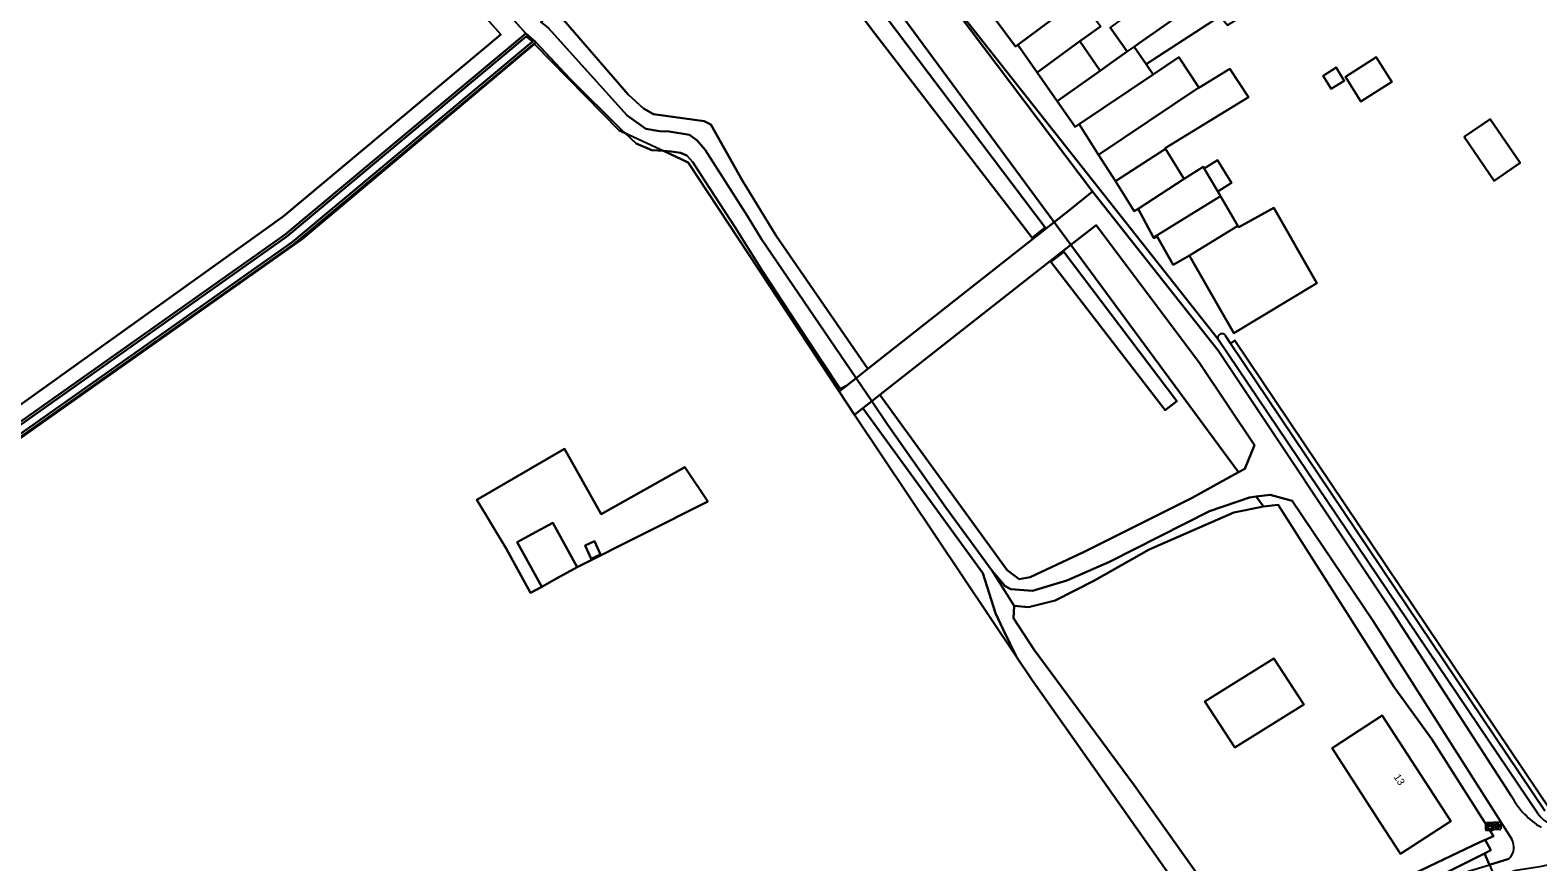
# Model space of a CAD drawing. Extents: x 163859 to 164644, y 379566 to 382155.
# Drawn here: x 164174.8 to 164380.2, y 381594.2 to 381707.4 of the extents above; entities that cross this region are included whole.
import ezdxf

# ---------------------------------------------------------------- set-up
doc = ezdxf.new("R2010")
doc.units = 0
for name, color, linetype in [('IMGEO_Bouwland', 7, 'Continuous'), ('IMGEO_Erf', 7, 'Continuous'), ('IMGEO_Grasland_overig', 7, 'Continuous'), ('IMGEO_Greppel_droge_sloot', 7, 'Continuous'), ('IMGEO_Groenvoorziening', 7, 'Continuous'), ('IMGEO_Haag', 7, 'Continuous'), ('IMGEO_Hek', 7, 'Continuous'), ('IMGEO_Kast', 7, 'Continuous'), ('IMGEO_Loofbos', 7, 'Continuous'), ('IMGEO_Oever', 7, 'Continuous'), ('IMGEO_Pand', 7, 'Continuous'), ('IMGEO_Pand_nummerreeks', 7, 'Continuous'), ('IMGEO_Rijbaan_lokaal_onverhard', 7, 'Continuous'), ('IMGEO_Rioolput', 7, 'Continuous'), ('IMGEO_Terreindeel_onvherhard', 7, 'Continuous'), ('IMGEO_Voetpad_onverhard', 7, 'Continuous'), ('IMGEO_Waterloop', 7, 'Continuous')]:
    doc.layers.add(name, color=color, linetype=linetype)

msp = doc.modelspace()

# ---------------------------------------------------------------- linework, layer by layer
at = {"layer": 'IMGEO_Bouwland'}
msp.add_lwpolyline([(164337.15, 381582.3), (164311.21, 381619.04), (164309.17, 381622.09), (164287.09, 381655.07), (164285.01, 381658.22), (164264.42, 381689.42), (164261.07, 381690.98), (164259.49, 381691.08), (164257.35, 381692.01), (164255.85, 381693.41), (164255.02, 381693.79), (164243.51, 381705.53), (164243.4, 381705.47), (164211.9, 381679.04), (164123.79, 381616.85)], dxfattribs=at)
msp.add_lwpolyline([(164239.63, 381636.86), (164235.65, 381643.49), (164247.59, 381650.43), (164252.57, 381641.51), (164264, 381647.94), (164267.11, 381643.27), (164249.31, 381634.3), (164246.48, 381632.75), (164244.48, 381631.65), (164242.95, 381630.81)], close=True, dxfattribs=at)
at = {"layer": 'IMGEO_Erf'}
for points in [[(164381.89, 381725.72), (164366.58, 381736.25), (164365.24, 381734.41), (164343.09, 381750), (164341.65, 381751.02), (164341.73, 381751.2), (164335.58, 381755.47), (164335.67, 381755.63), (164322.06, 381765.02), (164322.9, 381766.25), (164322.17, 381766.72), (164321.2, 381765.27), (164309.22, 381773.47), (164309.77, 381774.13), (164309.53, 381774.29), (164308.75, 381773.28), (164308.4, 381772.83), (164307.02, 381771.02), (164290.86, 381750), (164280.77, 381736.89), (164280.48, 381736.47), (164297.43, 381715.02), (164336.62, 381665.42)], [(164336.94, 381709.34), (164326.85, 381702.82), (164327.82, 381701.41), (164331.32, 381703.75), (164334.02, 381699.61), (164334.03, 381699.59), (164338.24, 381702.16), (164340.77, 381698.29), (164329.42, 381691.37), (164329.49, 381691.26), (164331.91, 381687.38), (164332.04, 381687.18), (164334.62, 381688.84), (164334.75, 381688.61), (164336.58, 381689.74), (164338.49, 381686.65), (164336.59, 381685.48), (164336.97, 381684.84), (164339.35, 381680.78), (164339.47, 381680.59), (164344.25, 381683.23), (164350.11, 381673), (164338.78, 381666.16), (164332.93, 381676.4), (164332.74, 381676.73), (164330.52, 381675.46), (164328.33, 381679.34), (164327.91, 381679.13), (164327.86, 381679.22), (164325.75, 381683.12), (164325.23, 381682.79), (164322.65, 381686.86), (164320.35, 381690.47), (164317.7, 381694.63), (164317.19, 381694.29), (164314.73, 381697.78), (164312.01, 381701.68), (164309.36, 381705.43), (164309.06, 381705.2), (164306.26, 381708.94)], [(164320.61, 381707.93), (164318.4, 381706.36), (164317.82, 381705.94), (164320.58, 381701.9), (164322.4, 381703.19), (164324.28, 381704.52), (164321.94, 381707.78)], [(164337.65, 381665.82), (164338.35, 381664.78), (164338.92, 381665.18), (164382.05, 381601.1), (164407.63, 381605.35), (164407.8, 381604.43), (164409.37, 381604.7), (164409.29, 381605.07), (164413.47, 381605.82), (164413.71, 381604.01), (164429.61, 381607.59), (164435.64, 381608.59)]]:
    msp.add_lwpolyline(points, dxfattribs=at)
for points in [[(164353.83, 381700.54), (164352.04, 381699.45), (164350.95, 381701.23), (164352.74, 381702.33)], [(164356.12, 381697.73), (164353.99, 381701.1), (164358.18, 381703.74), (164360.31, 381700.38)], [(164370.16, 381692.91), (164373.7, 381695.33), (164377.8, 381689.35), (164374.26, 381686.92)], [(164360.65, 381617.95), (164344.82, 381642.8), (164342.85, 381642.58), (164338.8, 381641.77), (164327.26, 381636.72), (164319.71, 381632.45), (164314.46, 381629.79), (164310.8, 381628.87), (164308.85, 381629.06), (164308.78, 381627.38), (164311.6, 381623.07), (164325.22, 381604.63), (164340.03, 381583.8), (164340.63, 381582.95), (164341.72, 381582.81), (164360.39, 381591.19), (164372.33, 381596.86), (164373.03, 381597.19), (164374.16, 381597.69), (164365.76, 381610.9)], [(164338.91, 381609.75), (164334.83, 381616.04), (164344.23, 381621.88), (164348.31, 381615.59)], [(164358.78, 381599.46), (164352.17, 381609.65), (164354.82, 381611.38), (164359.01, 381614.1), (164368.35, 381599.71), (164361.5, 381595.27)]]:
    msp.add_lwpolyline(points, close=True, dxfattribs=at)
msp.add_arc((164337.17, 381665.55), 0.556, 29.6547, 192.9812, dxfattribs=at)
at = {"layer": 'IMGEO_Grasland_overig'}
for points in [[(164246.32, 381710.17), (164244.37, 381708.52), (164244.89, 381708.11), (164245.41, 381707.7), (164256.11, 381695.82), (164258.69, 381693.98), (164260.55, 381693.7), (164261.84, 381693.63), (164264.63, 381693.16), (164265.68, 381692.42), (164266.74, 381691.13), (164272.54, 381682.12), (164274.44, 381678.97), (164287.33, 381660.05), (164288.9, 381661.31), (164276.44, 381679.42), (164271.82, 381687), (164267.52, 381694.58), (164266.6, 381695.05), (164259.73, 381695.98), (164258.36, 381696.75), (164256.26, 381698.68)], [(164286.07, 381659.06), (164285.16, 381658.59), (164280.25, 381666), (164274.54, 381674.72), (164270.81, 381680.67), (164266.71, 381686.93), (164265.08, 381689.47), (164264.27, 381690.36), (164263.4, 381690.74), (164262.13, 381690.91), (164261.07, 381690.98), (164264.42, 381689.42), (164285.01, 381658.22)], [(164316.58, 381678.2), (164314.3, 381681.31), (164288.9, 381661.31), (164287.33, 381660.05), (164289.46, 381656.93), (164290.56, 381657.79)], [(164287.33, 381660.05), (164286.07, 381659.06), (164285.01, 381658.22), (164287.09, 381655.07), (164288.22, 381655.95), (164289.46, 381656.93)], [(164288.22, 381655.95), (164287.09, 381655.07), (164309.17, 381622.09), (164307.37, 381625.84), (164306.3, 381628.05), (164304.6, 381633.51)]]:
    msp.add_lwpolyline(points, close=True, dxfattribs=at)
msp.add_lwpolyline([(164321.9, 381568.69), (164330.62, 381575.1), (164340.85, 381580.53), (164344.81, 381582.22), (164350.33, 381584.74), (164362.79, 381589.53), (164367.77, 381592.02), (164373.62, 381593.79), (164372.93, 381595.33), (164360.91, 381589.33), (164342.17, 381581.51), (164338.17, 381581.17), (164320.74, 381570.88), (164310.1, 381564.69), (164300.85, 381559.61), (164287.59, 381552.54), (164276.47, 381546.15), (164268.74, 381541.65), (164255.73, 381530.58), (164258.3, 381529.24)], dxfattribs=at)
at = {"layer": 'IMGEO_Greppel_droge_sloot'}
msp.add_lwpolyline([(164291.43, 381709.22), (164290.57, 381710.43), (164290.47, 381710.57), (164288.39, 381708.97), (164289.4, 381707.55), (164311.33, 381679.17), (164313.1, 381680.56)], close=True, dxfattribs=at)
at = {"layer": 'IMGEO_Groenvoorziening'}
for points in [[(164297.43, 381715.02), (164297.33, 381714.93), (164319.55, 381685.45), (164336.67, 381663.83), (164360.3, 381628.34), (164376.68, 381603.04)], [(164380.22, 381600.77), (164336.62, 381665.42), (164297.43, 381715.02)], [(164383.73, 381600.26), (164407.8, 381604.43), (164407.63, 381605.35), (164382.05, 381601.1), (164338.92, 381665.18), (164338.35, 381664.78)], [(164338.35, 381664.78), (164381.18, 381601.12)], [(164357.73, 381627.06), (164346.74, 381643.35), (164343.74, 381644.16), (164341.85, 381643.92), (164342.85, 381642.58), (164344.82, 381642.8), (164360.65, 381617.95), (164365.76, 381610.9), (164374.16, 381597.69), (164373.03, 381597.19), (164373.82, 381595.78), (164372.93, 381595.33), (164373.62, 381593.79), (164376.28, 381594.59)], [(164376.65, 381597.28), (164357.73, 381627.06)]]:
    msp.add_lwpolyline(points, dxfattribs=at)
for points in [[(164334.05, 381662.17), (164320.02, 381680.9), (164316.58, 381678.2), (164339.41, 381647.23), (164340.27, 381647.7), (164341.63, 381650.93)], [(164327.26, 381636.72), (164338.8, 381641.77), (164342.85, 381642.58), (164341.85, 381643.92), (164340.91, 381643.8), (164335.47, 381641.94), (164321.84, 381635.05), (164316.04, 381632.51), (164311.35, 381631.09), (164308.41, 381631.32), (164307.64, 381631.71), (164305.88, 381633.83), (164308.85, 381629.06), (164310.8, 381628.87), (164314.46, 381629.79), (164319.71, 381632.45)]]:
    msp.add_lwpolyline(points, close=True, dxfattribs=at)
for centre, radius, start, end in [((164386.24, 381608.19), 10.85, 208.3188, 239.0619), ((164383.39, 381602.82), 3.78, 212.9561, 287.5967), ((164374.79, 381596.17), 2.17, 313.3238, 30.8642)]:
    msp.add_arc(centre, radius, start, end, dxfattribs=at)
at = {"layer": 'IMGEO_Haag'}
for points in [[(164383.73, 381600.26), (164407.8, 381604.43), (164407.63, 381605.35), (164382.05, 381601.1), (164338.92, 381665.18), (164338.35, 381664.78)], [(164338.35, 381664.78), (164381.18, 381601.12)]]:
    msp.add_lwpolyline(points, dxfattribs=at)
at = {"layer": 'IMGEO_Hek'}
for points in [[(164285.01, 381658.22), (164264.42, 381689.42), (164255.02, 381693.79), (164243.51, 381705.53), (164243.36, 381705.52)], [(164287.09, 381655.07), (164285.01, 381658.22)]]:
    msp.add_lwpolyline(points, dxfattribs=at)
at = {"layer": 'IMGEO_Kast'}
for p, q in [((164373.2, 381599.49), (164374.04, 381599.49)), ((164374.04, 381599.49), (164373.2, 381599.49)), ((164373.12, 381598.57), (164373.12, 381599.41)), ((164373.12, 381599.41), (164373.12, 381598.57)), ((164374.05, 381598.49), (164373.21, 381598.49)), ((164373.21, 381598.49), (164374.05, 381598.49)), ((164374.12, 381599.42), (164374.12, 381598.58)), ((164374.12, 381598.58), (164374.12, 381599.42))]:
    msp.add_line(p, q, dxfattribs=at)
for points in [[(164373.32, 381599.28), (164373.92, 381599.28), (164373.92, 381599.2), (164373.32, 381599.2), (164373.32, 381599.28)], [(164373.32, 381599.11), (164373.92, 381599.11), (164373.92, 381598.62), (164373.32, 381598.62), (164373.32, 381599.11)]]:
    msp.add_lwpolyline(points, dxfattribs=at)
msp.add_circle((164373.4, 381598.96), 0.0377, dxfattribs=at)
for centre, start, end in [((164373.2, 381599.41), 92.4484, 184.2845), ((164373.2, 381599.41), 92.4484, 184.2845), ((164374.04, 381599.41), 2.4484, 94.2845), ((164374.04, 381599.41), 2.4484, 94.2845), ((164373.2, 381598.57), 182.4484, 274.2845), ((164373.2, 381598.57), 182.4484, 274.2845), ((164374.04, 381598.57), 272.4484, 4.2845), ((164374.04, 381598.57), 272.4484, 4.2845)]:
    msp.add_arc(centre, 0.0779, start, end, dxfattribs=at)
at = {"layer": 'IMGEO_Loofbos'}
for points in [[(164292.53, 381710.83), (164296.62, 381714.32), (164283.66, 381730.8), (164279.12, 381735.74), (164248.87, 381710.58), (164248.44, 381711.09), (164248.01, 381711.61), (164246.32, 381710.17), (164256.26, 381698.68), (164258.36, 381696.75), (164259.73, 381695.98), (164266.6, 381695.05), (164267.52, 381694.58), (164271.82, 381687), (164276.44, 381679.42), (164288.9, 381661.31), (164314.3, 381681.31)], [(164289.4, 381707.55), (164288.39, 381708.97), (164290.47, 381710.57), (164290.57, 381710.43), (164291.43, 381709.22), (164313.1, 381680.56), (164311.33, 381679.17)], [(164339.41, 381647.23), (164316.58, 381678.2), (164290.56, 381657.79), (164307.9, 381633.89), (164309.52, 381632.67), (164311.06, 381632.96), (164318.32, 381636.36), (164333.13, 381643.77)], [(164315.64, 381677.27), (164331.04, 381656.92), (164329.45, 381655.7), (164313.88, 381675.88)]]:
    msp.add_lwpolyline(points, close=True, dxfattribs=at)
msp.add_lwpolyline([(164162.11, 381648.34), (164209.26, 381682.06), (164238.9, 381706.83), (164214.34, 381734.46), (164210.77, 381733.46), (164209.5, 381733.38), (164208.24, 381733.18), (164207.01, 381732.88), (164205.81, 381732.47), (164204.64, 381731.95), (164204.45, 381731.85), (164130.93, 381680.28)], dxfattribs=at)
at = {"layer": 'IMGEO_Oever'}
for points in [[(164210.69, 381678.29), (164243.36, 381705.52), (164243.68, 381705.78), (164242.3, 381706.96), (164209.54, 381679.61), (164044.56, 381563.04), (164045.08, 381561.59)], [(164243.14, 381705.78), (164210.48, 381678.57), (164045.25, 381562.13), (164044.98, 381562.91), (164209.75, 381679.34), (164242.36, 381706.56), (164243.26, 381705.89)]]:
    msp.add_lwpolyline(points, close=True, dxfattribs=at)
at = {"layer": 'IMGEO_Pand'}
for points in [[(164347.48, 381714.07), (164344.1, 381718.5), (164334.47, 381711.7), (164325.91, 381705.67), (164325.22, 381705.18), (164326.85, 381702.82), (164336.94, 381709.34), (164337.91, 381708.11)], [(164334.47, 381711.7), (164333.03, 381713.59), (164331.95, 381715), (164321.94, 381707.78), (164324.28, 381704.52), (164325.22, 381705.18), (164325.91, 381705.67)], [(164316.22, 381710.54), (164313.3, 381714.42), (164306.26, 381708.94), (164309.06, 381705.2), (164309.36, 381705.43)], [(164316.22, 381710.54), (164309.36, 381705.43), (164312.01, 381701.68), (164317.82, 381705.94), (164318.4, 381706.36), (164320.61, 381707.93), (164317.82, 381711.73)], [(164317.82, 381705.94), (164312.01, 381701.68), (164314.73, 381697.78), (164320.58, 381701.9)], [(164327.82, 381701.41), (164326.85, 381702.82), (164325.22, 381705.18), (164324.28, 381704.52), (164322.4, 381703.19), (164320.58, 381701.9), (164314.73, 381697.78), (164317.19, 381694.29), (164317.7, 381694.63)], [(164334.02, 381699.61), (164331.32, 381703.75), (164327.82, 381701.41), (164317.7, 381694.63), (164320.35, 381690.47)], [(164322.65, 381686.86), (164329.49, 381691.26), (164329.42, 381691.37), (164340.77, 381698.29), (164338.24, 381702.16), (164334.03, 381699.59), (164334.02, 381699.61), (164320.35, 381690.47)], [(164350.95, 381701.23), (164352.04, 381699.45), (164353.83, 381700.54), (164352.74, 381702.33)], [(164358.18, 381703.74), (164353.99, 381701.1), (164356.12, 381697.73), (164360.31, 381700.38)], [(164370.16, 381692.91), (164374.26, 381686.92), (164377.8, 381689.35), (164373.7, 381695.33)], [(164332.04, 381687.18), (164331.91, 381687.38), (164329.49, 381691.26), (164322.65, 381686.86), (164325.23, 381682.79), (164325.75, 381683.12)], [(164336.97, 381684.84), (164336.59, 381685.48), (164334.75, 381688.61), (164334.62, 381688.84), (164332.04, 381687.18), (164325.75, 381683.12), (164327.86, 381679.22)], [(164334.75, 381688.61), (164336.59, 381685.48), (164338.49, 381686.65), (164336.58, 381689.74)], [(164327.86, 381679.22), (164327.91, 381679.13), (164328.33, 381679.34), (164330.52, 381675.46), (164332.74, 381676.73), (164339.35, 381680.78), (164336.97, 381684.84)], [(164339.35, 381680.78), (164332.74, 381676.73), (164332.93, 381676.4), (164338.78, 381666.16), (164350.11, 381673), (164344.25, 381683.23), (164339.47, 381680.59)], [(164244.48, 381631.65), (164246.48, 381632.75), (164249.31, 381634.3), (164245.99, 381640.35), (164243.15, 381638.8), (164241.16, 381637.7)], [(164250.4, 381637.24), (164251.23, 381635.44), (164252.51, 381636.03), (164251.69, 381637.84)], [(164338.91, 381609.75), (164348.31, 381615.59), (164344.23, 381621.88), (164334.83, 381616.04)], [(164361.5, 381595.27), (164368.35, 381599.71), (164359.01, 381614.1), (164354.82, 381611.38), (164352.17, 381609.65), (164358.78, 381599.46)]]:
    msp.add_lwpolyline(points, close=True, dxfattribs=at)
at = {"layer": 'IMGEO_Rijbaan_lokaal_onverhard'}
msp.add_lwpolyline([(164297.33, 381714.93), (164296.62, 381714.32), (164292.53, 381710.83), (164314.3, 381681.31), (164316.43, 381682.99), (164319.55, 381685.45)], close=True, dxfattribs=at)
for points in [[(164376.68, 381603.04), (164360.3, 381628.34), (164336.67, 381663.83), (164319.55, 381685.45), (164316.43, 381682.99), (164314.3, 381681.31), (164316.58, 381678.2), (164320.02, 381680.9), (164334.05, 381662.17), (164341.63, 381650.93), (164340.27, 381647.7), (164339.41, 381647.23), (164333.13, 381643.77), (164318.32, 381636.36), (164311.06, 381632.96), (164309.52, 381632.67), (164307.9, 381633.89), (164290.56, 381657.79), (164289.46, 381656.93), (164291.61, 381653.76), (164299.54, 381642.42), (164305.88, 381633.83), (164307.64, 381631.71), (164308.41, 381631.32), (164311.35, 381631.09), (164316.04, 381632.51), (164321.84, 381635.05), (164335.47, 381641.94), (164340.91, 381643.8), (164341.85, 381643.92), (164343.74, 381644.16), (164346.74, 381643.35), (164357.73, 381627.06), (164376.65, 381597.28)], [(164376.28, 381594.59), (164373.62, 381593.79), (164374.37, 381592.06), (164377.23, 381593.05), (164380.51, 381593.56), (164384.86, 381594.48), (164414.14, 381600.68)]]:
    msp.add_lwpolyline(points, dxfattribs=at)
for centre, radius, start, end in [((164386.24, 381608.19), 10.85, 208.3188, 239.0619), ((164374.79, 381596.17), 2.17, 313.3238, 30.8642)]:
    msp.add_arc(centre, radius, start, end, dxfattribs=at)
at = {"layer": 'IMGEO_Rioolput'}
for p, q in [((164374.16, 381598.66), (164374.16, 381599.51)), ((164374.23, 381599.59), (164375.08, 381599.59)), ((164375.16, 381599.51), (164375.16, 381598.66)), ((164375.08, 381598.59), (164374.23, 381598.59)), ((164374.41, 381599.08), (164374.41, 381599.09)), ((164374.85, 381599.04), (164374.45, 381599.04)), ((164374.46, 381599.13), (164374.85, 381599.13)), ((164374.64, 381599.37), (164374.67, 381599.37)), ((164374.67, 381598.81), (164374.64, 381598.81)), ((164374.9, 381599.09), (164374.9, 381599.08))]:
    msp.add_line(p, q, dxfattribs=at)
for points in [[(164374.16, 381598.66), (164374.16, 381599.51)], [(164374.23, 381599.59), (164375.08, 381599.59)], [(164375.16, 381599.51), (164375.16, 381598.66)], [(164375.08, 381598.59), (164374.23, 381598.59)]]:
    msp.add_lwpolyline(points, dxfattribs=at)
for centre, radius, start, end in [((164374.23, 381599.51), 0.0765, 91.552, 178.448), ((164374.23, 381599.51), 0.0765, 91.552, 178.448), ((164375.08, 381599.51), 0.0765, 1.552, 88.448), ((164375.08, 381599.51), 0.0765, 1.552, 88.448), ((164374.23, 381598.66), 0.0765, 181.552, 268.448), ((164374.23, 381598.66), 0.0765, 181.552, 268.448), ((164374.45, 381599.09), 0.0403, 85.8775, 175.7526), ((164374.45, 381599.08), 0.0366, 178.938, 274.7102), ((164374.86, 381599.09), 0.0386, 1.7309, 96.639), ((164374.86, 381599.09), 0.043, 264.8664, 352.4533), ((164375.08, 381598.66), 0.0765, 271.552, 358.448), ((164375.08, 381598.66), 0.0765, 271.552, 358.448)]:
    msp.add_arc(centre, radius, start, end, dxfattribs=at)
for centre, major_axis, ratio, start_param, end_param in [((164374.64, 381599.09), (-0.387, 0.002), 0.722429, 4.712389, 7.853982), ((164374.67, 381599.09), (-0.39, 0.002), 0.717154, 1.570796, 4.712389)]:
    msp.add_ellipse(centre, major_axis=major_axis, ratio=ratio, start_param=start_param, end_param=end_param, dxfattribs=at)
at = {"layer": 'IMGEO_Terreindeel_onvherhard'}
for points in [[(164247.59, 381650.43), (164235.65, 381643.49), (164239.63, 381636.86), (164242.95, 381630.81), (164244.48, 381631.65), (164241.16, 381637.7), (164243.15, 381638.8), (164245.99, 381640.35), (164249.31, 381634.3), (164267.11, 381643.27), (164264, 381647.94), (164252.57, 381641.51)], [(164251.69, 381637.84), (164252.51, 381636.03), (164251.23, 381635.44), (164250.4, 381637.24)]]:
    msp.add_lwpolyline(points, close=True, dxfattribs=at)
at = {"layer": 'IMGEO_Voetpad_onverhard'}
for points in [[(164044.56, 381563.04), (164209.54, 381679.61), (164242.3, 381706.96), (164217.89, 381734.38)], [(164130.93, 381680.28), (164204.45, 381731.85), (164204.64, 381731.95), (164205.81, 381732.47), (164207.01, 381732.88), (164208.24, 381733.18), (164209.5, 381733.38), (164210.77, 381733.46), (164214.34, 381734.46), (164238.9, 381706.83), (164209.26, 381682.06), (164162.11, 381648.34)], [(164123.79, 381616.85), (164211.9, 381679.04), (164243.4, 381705.47), (164243.51, 381705.53), (164255.02, 381693.79), (164255.85, 381693.41), (164255.36, 381693.87), (164248.33, 381700.83), (164243.68, 381705.78), (164243.36, 381705.52), (164210.69, 381678.29), (164045.08, 381561.59)]]:
    msp.add_lwpolyline(points, dxfattribs=at)
at = {"layer": 'IMGEO_Waterloop'}
for points in [[(164217.89, 381734.38), (164242.3, 381706.96), (164243.68, 381705.78), (164248.33, 381700.83), (164255.36, 381693.87), (164255.85, 381693.41), (164257.35, 381692.01), (164259.49, 381691.08), (164261.07, 381690.98), (164262.13, 381690.91), (164263.4, 381690.74), (164264.27, 381690.36), (164265.08, 381689.47), (164266.71, 381686.93), (164270.81, 381680.67), (164274.54, 381674.72), (164280.25, 381666), (164285.16, 381658.59), (164286.07, 381659.06), (164287.33, 381660.05), (164274.44, 381678.97), (164272.54, 381682.12), (164266.74, 381691.13), (164265.68, 381692.42), (164264.63, 381693.16), (164261.84, 381693.63), (164260.55, 381693.7), (164258.69, 381693.98), (164256.11, 381695.82), (164245.41, 381707.7)], [(164336.62, 381665.42), (164380.22, 381600.77)], [(164338.35, 381664.78), (164337.65, 381665.82)], [(164381.18, 381601.12), (164338.35, 381664.78)], [(164340.03, 381583.8), (164325.22, 381604.63), (164311.6, 381623.07), (164308.78, 381627.38), (164308.85, 381629.06), (164305.88, 381633.83), (164299.54, 381642.42), (164291.61, 381653.76), (164289.46, 381656.93), (164288.22, 381655.95), (164304.6, 381633.51), (164306.3, 381628.05), (164307.37, 381625.84), (164309.17, 381622.09), (164311.21, 381619.04), (164337.15, 381582.3)], [(164360.91, 381589.33), (164372.93, 381595.33), (164373.82, 381595.78), (164373.03, 381597.19), (164372.33, 381596.86), (164360.39, 381591.19)]]:
    msp.add_lwpolyline(points, dxfattribs=at)
for points in [[(164243.14, 381705.78), (164243.26, 381705.89), (164242.36, 381706.56), (164209.75, 381679.34), (164044.98, 381562.91), (164045.25, 381562.13), (164210.48, 381678.57)], [(164315.64, 381677.27), (164313.88, 381675.88), (164329.45, 381655.7), (164331.04, 381656.92)]]:
    msp.add_lwpolyline(points, close=True, dxfattribs=at)
for centre, radius, start, end in [((164337.17, 381665.55), 0.556, 29.6547, 192.9812), ((164383.39, 381602.82), 3.78, 212.9561, 287.5967)]:
    msp.add_arc(centre, radius, start, end, dxfattribs=at)

# ---------------------------------------------------------------- texts
at = {"layer": 'IMGEO_Pand_nummerreeks'}
msp.add_text('13', height=1, rotation=302.9942, dxfattribs=at).set_placement((164360.53, 381605.74))

doc.saveas('drawing.dxf')
